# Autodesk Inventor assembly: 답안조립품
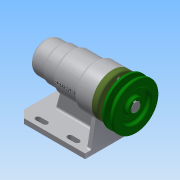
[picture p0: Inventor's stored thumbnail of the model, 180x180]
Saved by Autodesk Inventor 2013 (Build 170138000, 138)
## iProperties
Created: 2017-09
Part Number: 답안조립품
Document SubType Name: Assembly
Designer: Administrator
Author: Administrator
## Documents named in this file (12)
- C:\Users\Administrator\Desktop\470908V1009\답안조립품.iam
- C:\Users\Administrator\Desktop\470908V1009\본체.ipt
- C:\Users\Administrator\Desktop\470908V1009\V벨트풀리.ipt
- C:\Users\Administrator\Desktop\470908V1009\멈춤나사 M3x8.ipt
- C:\Users\Administrator\Desktop\470908V1009\베어링 6004.ipt
- C:\Users\Administrator\Desktop\470908V1009\베어링 51202.ipt
- C:\Users\Administrator\Desktop\470908V1009\볼트 M4 x 12.ipt
- C:\Users\Administrator\Desktop\470908V1009\어댑터슬리브.ipt
- C:\Users\Administrator\Desktop\470908V1009\오일 실 20x35x7.ipt
- C:\Users\Administrator\Desktop\470908V1009\축.ipt
- C:\Users\Administrator\Desktop\470908V1009\커버.ipt
- C:\Users\Administrator\Desktop\470908V1009\키 5 x 5 x 16.ipt
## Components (1 placed, 1 different names)
1. V벨트풀리:1 — 각도:3
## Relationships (1: Angle 1)
- 각도:3 [Angle]: V벨트풀리:1
